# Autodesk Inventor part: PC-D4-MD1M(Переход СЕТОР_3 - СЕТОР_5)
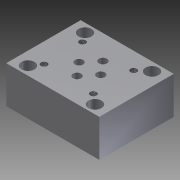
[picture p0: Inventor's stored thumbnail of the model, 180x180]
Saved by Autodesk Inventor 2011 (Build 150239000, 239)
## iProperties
Created: 2011-12
Part Number: PC-D4-MD1M(Переход СЕТОР_3 - СЕТОР_5)
Document SubType Name: Modeling
Designer: khramov
Density: 1 g/cm^3
Author: khramov
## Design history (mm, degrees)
sketch "Эскиз1"
  geometry: L1 (0, 0)-(75, 0); L2 (75, 0)-(75, -60); L3 (75, -60)-(0, -60); L4 (0, -60)-(0, 0); L5 (10.5, -7)-(64.5, -7); L6 (64.5, -7)-(64.5, -53); L7 (64.5, -53)-(10.5, -53); L8 (10.5, -53)-(10.5, -7); L9 (37.5, -7)-(37.5, 0); L10 (10.5, -30)-(0, -30); C1 r 3.25 at (10.5, -7); C2 r 3.25 at (64.5, -7); C3 r 3.25 at (64.5, -53); C4 r 3.25 at (10.5, -53)
  constraints: 20 end point, 4 centre point, 4 coincident, 4 midpoint, 4 parallel, 3 horizontal, 2 perpendicular, 1 vertical
  dimensions: "d0" = 75 distance of L1.start L1.end; "d1" = 60 distance of L3.end L1.start; "d2" = 46 distance of L7.end L5.start; "d3" = 54 distance of L5.start L5.end; "d4" = 10.5 distance between parallel lines of L4 L8 (derived); "d5" = 7 distance between parallel lines of L5 L1 (derived); "d6" = 6.5 diameter of C1; "d7" = 6.5 diameter of C2; "d8" = 6.5 diameter of C3; "d9" = 6.5 diameter of C4
extrude "Выдавливание1" new body sketch "Эскиз1" distance "d10" = 30; taper "d11" = 0 deg
sketch "Эскиз2"
  geometry: C1 r 3.25 at (10.5, -53) reference; C2 r 3.25 at (64.5, -53) reference; C3 r 3.25 at (64.5, -7) reference; C4 r 3.25 at (10.5, -7) reference; C5 r 5.25 at (10.5, -53); C6 r 5.25 at (10.5, -7); C7 r 5.25 at (64.5, -7); C8 r 5.25 at (64.5, -53)
  constraints: 4 centre point, 4 coincident
  dimensions: "d12" = 10.5 diameter of C5; "d13" = 10.5 diameter of C6; "d14" = 10.5 diameter of C7; "d15" = 10.5 diameter of C8
extrude "Выдавливание2" cut sketch "Эскиз2" distance "d16" = 14; taper "d17" = 0 deg
derived "Место под  CETOP03.ipt"
feature "Переместить тело1"
feature "Комбинировать1"
  node "Твердое тело2"
derived "Место под  CETOP05.ipt"
feature "Переместить тело2"
feature "Комбинировать2"
  node "Твердое тело3"
node "Твердое тело1"
feature "Твердое тело1::Место под  CETOP03.ipt" dims "d18" = 10
tag "Элемент создания маркировки1"
feature "Твердое тело1::Место под  CETOP05.ipt" dims "d22" = 10
tag "Элемент создания маркировки2"
other parameters: "d19" = 16, "d20" = -14.5, "d21" = 25, "d23" = 10.5, "d24" = -7, "d25" = 0
